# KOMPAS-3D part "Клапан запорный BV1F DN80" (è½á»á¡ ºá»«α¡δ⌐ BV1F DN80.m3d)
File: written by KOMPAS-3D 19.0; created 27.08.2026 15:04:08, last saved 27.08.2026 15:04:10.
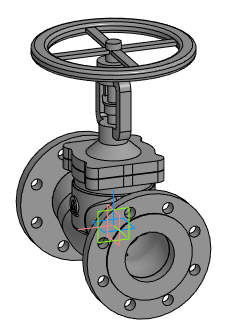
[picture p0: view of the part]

Document properties: Автор: Энергия; Полное имя файла: E:\Dendor\_3D для проектировщиков\5.6 Клапан запорный BV1F\stp\Клапан запорный BV1F DN80.m3d

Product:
- Part/product: Клапан запорный BV1F DN80
    Масса: 30.0427

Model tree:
1. Операция без истории:1  (labels: 7Ā7␣6␣6Ā7␣6Ā7Ȁ7␣6␣6Ȁ7␣6Ȁ7̀7␣6␣6̀7␣6̀7Ѐ7␣6␣6Ѐ7␣6Ѐ7␣6␣6␣)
